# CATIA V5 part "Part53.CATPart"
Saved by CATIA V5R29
Part number: Bottom Cover and fix
Revision: ANY
Definition: UNKNOWN
Nomenclature: Bottom Cover and fix
Source: Unknown
Bounding box of the stored display mesh (mm): x -41.99 to 41.998, y -31.34 to 10, z -22 to 22
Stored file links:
  C:\Users\Administrator\Desktop\프로젝트\Gripper\Part53.CATPart
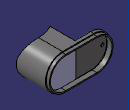
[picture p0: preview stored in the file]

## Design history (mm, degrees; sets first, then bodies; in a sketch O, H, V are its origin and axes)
Set1
  Sketch1 on face of Solid1, origin (0, 0, 0), H (0, 0, 1), V (-1, 0, 0)
    projected arc E1 centre (0, -20) radius 22 from (-22, -20) to (22, -20) ccw from edge [face of Solid1 | face of Solid1]
    line L1 (-22, -20) -> (-22, 0)
    point P3 (-22, 0)
    line L2 (-22, 0) -> (22, 0)
    line L3 (22, 0) -> (22, -20)
    tangency: L1 E1
    coincidence: P3 H
    horizontal: L2 H
    vertical: L3 V, L1 V
Body1 "Fillet4" (main body)
  Solid1: solid without history
  DatumSurface1
  DatumSurface2
  Pad1: profile Sketch1, direction (0, -1, 0), up to face of DatumSurface2, opposite side length 3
